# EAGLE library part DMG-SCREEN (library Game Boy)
The white connector for the ribbon cable to connect the DMG's front half
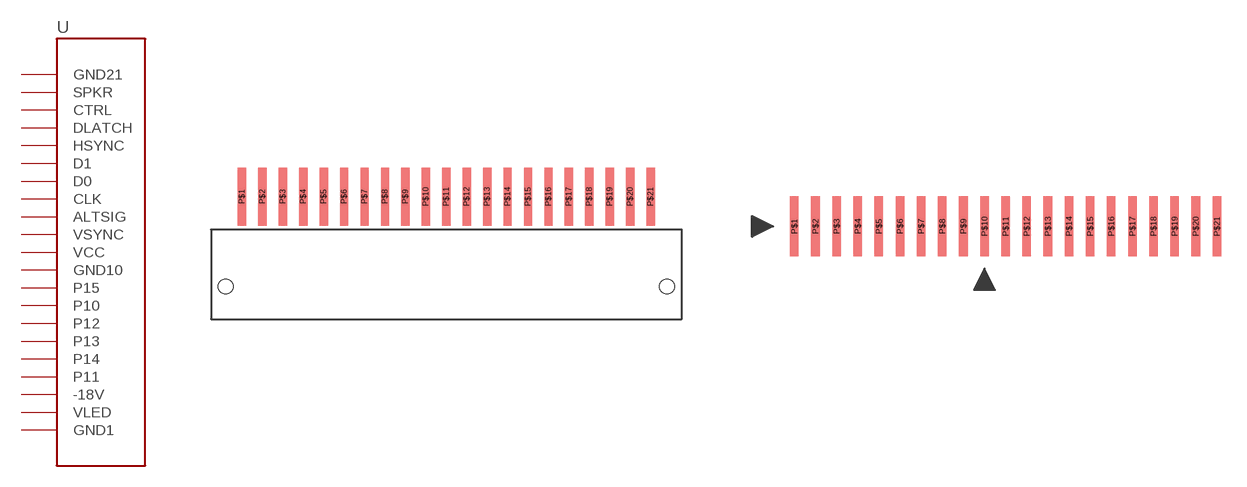
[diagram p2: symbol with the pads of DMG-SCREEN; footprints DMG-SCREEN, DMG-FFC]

Designator prefix -

## DMG-SCREENCONNECTOR  [DMG-SCREEN]
P$1  GND1
P$2  VLED
P$3  -18V
P$4  P11
P$5  P14
P$6  P13
P$7  P12
P$8  P10
P$9  P15
P$10  GND10
P$11  VCC
P$12  VSYNC
P$13  ALTSIG
P$14  CLK
P$15  D0
P$16  D1
P$17  HSYNC
P$18  DLATCH
P$19  CTRL
P$20  SPKR
P$21  GND21

## DMG-SCREENFFC  [DMG-FFC]
Pads as for DMG-SCREEN

## Footprint DMG-SCREEN (pad centres in mm)
smd 0.508 x 3.556: P$1 -12.5,0; P$2 -11.25,0; P$3 -10,0; P$4 -8.75,0; P$5 -7.5,0; P$6 -6.25,0; P$7 -5,0; P$8 -3.75,0; P$9 -2.5,0; P$10 -1.25,0; P$11 0,0; P$12 1.25,0; P$13 2.5,0; P$14 3.75,0; P$15 5,0; P$16 6.25,0; P$17 7.5,0; P$18 8.75,0; P$19 10,0; P$20 11.25,0; P$21 12.5,0
hole 0.9 at -13.5,-5.5
hole 0.9 at 13.5,-5.5

## Footprint DMG-FFC (pad centres in mm)
smd 0.508 x 3.556: P$1 -12.5,0; P$2 -11.25,0; P$3 -10,0; P$4 -8.75,0; P$5 -7.5,0; P$6 -6.25,0; P$7 -5,0; P$8 -3.75,0; P$9 -2.5,0; P$10 -1.25,0; P$11 0,0; P$12 1.25,0; P$13 2.5,0; P$14 3.75,0; P$15 5,0; P$16 6.25,0; P$17 7.5,0; P$18 8.75,0; P$19 10,0; P$20 11.25,0; P$21 12.5,0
